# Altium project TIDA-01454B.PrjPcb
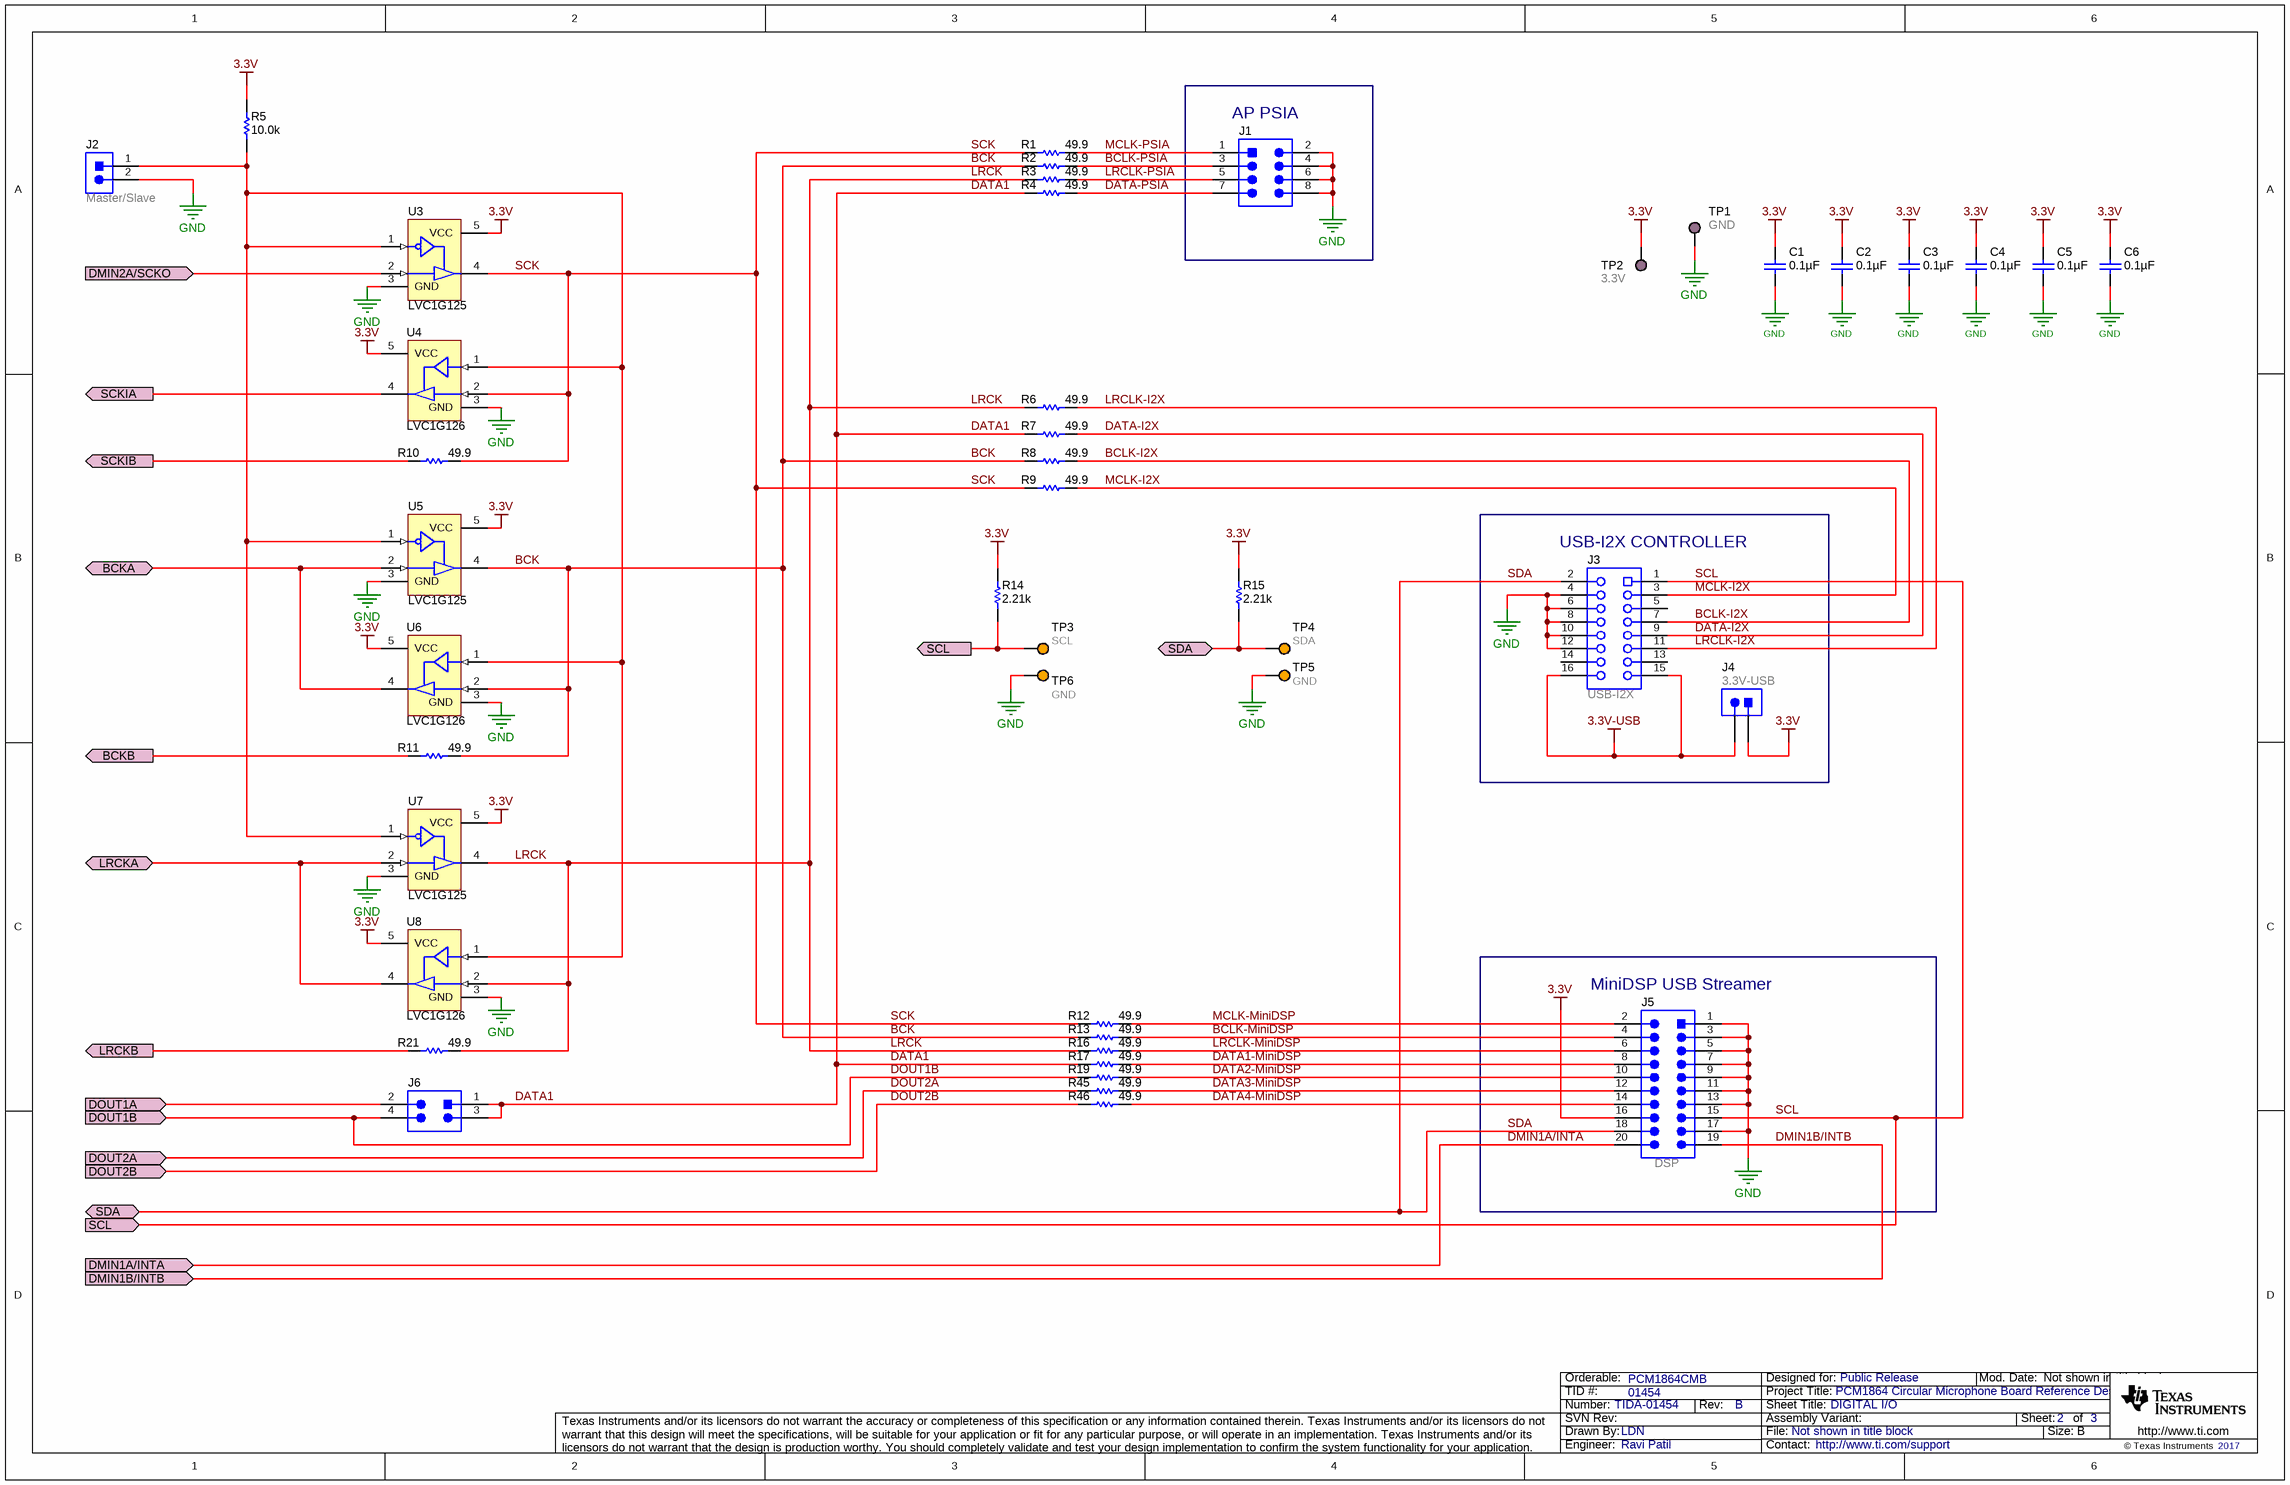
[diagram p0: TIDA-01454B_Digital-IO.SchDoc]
CopyrightYear: 2017; EVM_Orderable: PCM1864CMB; PCB_Layout: LDN; PCB_Rev: B; PRJ_Customer: Public Release; PRJ_Engineer: Ravi Patil; PRJ_Number: TIDA-01454; PRJ_Title: PCM1864 Circular Microphone Board Reference Design; SCH_Rev: B; TechSupport: http://www.ti.com/support; TID: 01454
3 sheets, 209 parts. Net scope: flat (ports and power ports of the same name join across sheets).
Board file: TIDA-01454B_PCB.PcbDoc
Sheets:
  TIDA-01454B_Digital-IO.SchDoc
  TIDA-01454B_Hardware.SchDoc
  TIDA-01454B_Main-IO.SchDoc

## Sheet TIDA-01454B_Digital-IO.SchDoc: DIGITAL I/O
size 431 x 279 mm; Date: Not shown in title block; ApprovedBy: Not shown in title block; CheckedBy: Not shown in title block; Author: Not shown in title block; CompanyName: Not shown in title block; DrawnBy: LDN; Engineer: Not shown in title block; Organization: Not shown in title block; Address1: Not shown in title block; Address2: Not shown in title block; Address3: Not shown in title block; Address4: Not shown in title block; DocumentNumber: 2; Revision: Use project parameter SCH_Rev; SheetNumber: 2; SheetTotal: 3; PageSetup: Record=PageOptions¦CenterHorizontal=True¦CenterVertical=True¦PrintScale=1.00¦XCorrection=1.00¦YCorrection=1.00¦PrintKind=0¦BorderSize=5000000¦LeftOffset=0¦BottomOffset=0¦Orientation=2¦PaperLength=1000¦PaperWidth=1000¦Scale=100¦PaperSource=15¦PrintQuality=600¦MediaType=1¦DitherType=10¦PaperKind=Letter¦PrintScaleMode=1

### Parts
C1  ValueDisplayed: 0.1µF  [0603L]  (hidden comment: GRM188R71C104KA01D)
C2  ValueDisplayed: 0.1µF  [0603L]  (hidden comment: GRM188R71C104KA01D)
C3  ValueDisplayed: 0.1µF  [0603L]  (hidden comment: GRM188R71C104KA01D)
C4  ValueDisplayed: 0.1µF  [0603L]  (hidden comment: GRM188R71C104KA01D)
C5  ValueDisplayed: 0.1µF  [0603L]  (hidden comment: GRM188R71C104KA01D)
C6  ValueDisplayed: 0.1µF  [0603L]  (hidden comment: GRM188R71C104KA01D)
J1  DNP  [CONN_PEC04DAAN]  (value not drawn)
J2  Master/Slave  [Sullins_PBC02SAAN]
J3  USB-I2X  [Sullins_PPPC082LJBN-RC]
J4  3.3V-USB  [Sullins_PBC02SAAN]
J5  DSP  [TSW-110-07-G-D]
J6  PBC02DAAN  [Sullins_PxC02DAAN]  (value not drawn)
R1  ValueDisplayed: 49.9  [0402L]  (hidden comment: RC0402FR-0749R9L)
R2  ValueDisplayed: 49.9  [0402L]  (hidden comment: RC0402FR-0749R9L)
R3  ValueDisplayed: 49.9  [0402L]  (hidden comment: RC0402FR-0749R9L)
R4  ValueDisplayed: 49.9  [0402L]  (hidden comment: RC0402FR-0749R9L)
R5  ValueDisplayed: 10.0k  [0603L]  (hidden comment: ERJ-3EKF1002V)
R6  ValueDisplayed: 49.9  [0402L]  (hidden comment: RC0402FR-0749R9L)
R7  ValueDisplayed: 49.9  [0402L]  (hidden comment: RC0402FR-0749R9L)
R8  ValueDisplayed: 49.9  [0402L]  (hidden comment: RC0402FR-0749R9L)
R9  ValueDisplayed: 49.9  [0402L]  (hidden comment: RC0402FR-0749R9L)
R10  ValueDisplayed: 49.9  [0402L]  (hidden comment: RC0402FR-0749R9L)
R11  ValueDisplayed: 49.9  [0402L]  (hidden comment: RC0402FR-0749R9L)
R12  ValueDisplayed: 49.9  [0402L]  (hidden comment: RC0402FR-0749R9L)
R13  ValueDisplayed: 49.9  [0402L]  (hidden comment: RC0402FR-0749R9L)
R14  ValueDisplayed: 2.21k  [0402L]  (hidden comment: CRCW04022K21FKED)
R15  ValueDisplayed: 2.21k  [0402L]  (hidden comment: CRCW04022K21FKED)
R16  ValueDisplayed: 49.9  [0402L]  (hidden comment: RC0402FR-0749R9L)
R17  ValueDisplayed: 49.9  [0402L]  (hidden comment: RC0402FR-0749R9L)
R19  ValueDisplayed: 49.9  [0402L]  (hidden comment: RC0402FR-0749R9L)
R21  ValueDisplayed: 49.9  [0402L]  (hidden comment: RC0402FR-0749R9L)
R45  ValueDisplayed: 49.9  [0402L]  (hidden comment: RC0402FR-0749R9L)
R46  ValueDisplayed: 49.9  [0402L]  (hidden comment: RC0402FR-0749R9L)
TP1  GND  [TestPoint_50x20-TH]
TP2  3.3V  [TestPoint_50x20-TH]
TP3  SCL  [TestPoint_50x30-TH]
TP4  SDA  [TestPoint_50x30-TH]
TP5  GND  [TestPoint_50x30-TH]
TP6  GND  [TestPoint_50x30-TH]
U3  LVC1G125  [DCK0005A_N]
U4  LVC1G126  [DCK0005A_N]
U5  LVC1G125  [DCK0005A_N]
U6  LVC1G126  [DCK0005A_N]
U7  LVC1G125  [DCK0005A_N]
U8  LVC1G126  [DCK0005A_N]

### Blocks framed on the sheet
AP PSIA: J1
USB-I2X CONTROLLER: J3 J4
MiniDSP USB Streamer: J5

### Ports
BCKA (bidir), BCKB (out), DMIN1A/INTA (in), DMIN1B/INTB (in), DMIN2A/SCKO (in), DOUT1A (in), DOUT1B (in), DOUT2A (in), DOUT2B (in), LRCKA (bidir), LRCKB (out), SCKIA (out), SCKIB (out), SCL (in), SCL (out), SDA (bidir)

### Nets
3.3V: C1.2 C2.2 C3.2 C4.2 C5.2 C6.2 J4.1 J5.16 R5.2 R14.1 R15.1 TP2.1 U3.5(VCC) U4.5(VCC) U5.5(VCC) U6.5(VCC) U7.5(VCC) U8.5(VCC)
3.3V-USB: J3.15 J3.16 J4.2
GND: C1.1 C2.1 C3.1 C4.1 C5.1 C6.1 J1.2 J1.4 J1.6 J1.8 J2.2 J3.4 J3.6 J3.8 J3.10 J3.12 J5.1 J5.3 J5.5 J5.7 J5.9 J5.11 J5.13 J5.17 TP1.1 TP5.1 TP6.1 U3.3(GND) U4.3(GND) U5.3(GND) U6.3(GND) U7.3(GND) U8.3(GND)
BCK: R2.1 R8.1 R11.2 R13.1 U5.4(Y) U6.2(A)
BCKA: U5.2(A) U6.4(Y) ; port BCKA
BCKB: R11.1 ; port BCKB
BCLK-I2X: J3.7 R8.2
BCLK-MiniDSP: J5.4 R13.2
BCLK-PSIA: J1.3 R2.2
DATA1: J6.1 J6.3 R4.1 R7.1 R17.1
DATA1-MiniDSP: J5.8 R17.2
DATA2-MiniDSP: J5.10 R19.2
DATA3-MiniDSP: J5.12 R45.2
DATA4-MiniDSP: J5.14 R46.2
DATA-I2X: J3.9 R7.2
DATA-PSIA: J1.7 R4.2
DMIN1A/INTA: J5.20 ; port DMIN1A/INTA
DMIN1B/INTB: J5.19 ; port DMIN1B/INTB
DMIN2A/SCKO: U3.2(A) ; port DMIN2A/SCKO
DOUT1A: J6.2 ; port DOUT1A
DOUT1B: J6.4 R19.1 ; port DOUT1B
DOUT2A: R45.1 ; port DOUT2A
DOUT2B: R46.1 ; port DOUT2B
LRCK: R3.1 R6.1 R16.1 R21.2 U7.4(Y) U8.2(A)
LRCKA: U7.2(A) U8.4(Y) ; port LRCKA
LRCKB: R21.1 ; port LRCKB
LRCLK-I2X: J3.11 R6.2
LRCLK-MiniDSP: J5.6 R16.2
LRCLK-PSIA: J1.5 R3.2
MCLK-I2X: J3.3 R9.2
MCLK-MiniDSP: J5.2 R12.2
MCLK-PSIA: J1.1 R1.2
SCK: R1.1 R9.1 R10.2 R12.1 U3.4(Y) U4.2(A)
SCKIA: U4.4(Y) ; port SCKIA
SCKIB: R10.1 ; port SCKIB
SCL: J3.1 J5.15 R14.2 TP3.1 ; port SCL
SDA: J3.2 J5.18 R15.2 TP4.1 ; port SDA
NetJ2_1: J2.1 R5.1 U3.1(~{OE}) U4.1(~{OE}) U5.1(~{OE}) U6.1(~{OE}) U7.1(~{OE}) U8.1(~{OE})

Not connected (* = marked no-connect by the designer): J3 5 13 14

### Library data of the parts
C1-C6 = GRM188R71C104KA01D: CAP, CERM, 0.1 µF, 16 V, +/- 10%, X7R, 0603; Manufacturer: MuRata; Polarized: N; CompType: Capacitor; Value: 0.1uF; U/M: EA; Cap_F: 0.0000001; Tolerance_%: 10; Value1: Unknown; VDC_V: 16; Value2: 16V; TaMin_C: -55; TaMax_C: 125; Cap_Case: 0603; SizeArea_mm2: 1.28; SizeAreaWB_mm2: 4.68; SizeX_mm: 1.6; SizeY_mm: 0.8; SizeZ_mm: 1; AEC Category: Q200
J1 = PEC04DAAN: Header, 100mil, 4x2, Tin, TH; Manufacturer: Sullins Connector Solutions; SymbolCreator: a0411947; Pitch_mm: 2.54; Gender: Male; Shrouded: N; Row_Count: 2; Current_A: 3; Voltage_V: 1800; Cert_UL: Y
J2 J4 = PBC02SAAN: Header, 100mil, 2x1, Gold, TH; Manufacturer: Sullins Connector Solutions; SymbolCreator: a0412235; Pitch_mm: 2.54; Gender: Male; Shrouded: N; Row_Count: 1; Current_A: 3; Voltage_V: 1800; Cert_UL: Y
J3 = PPPC082LJBN-RC: Receptacle, 100mil, 8x2, Gold, R/A, TH; Manufacturer: Sullins Connector Solutions; SymbolCreator: a0411947
J5 = TSW-110-07-G-D: Header, 100mil, 10x2, Gold, TH; Manufacturer: Samtec; SymbolCreator: a0412235; Pitch_mm: 2.54; Gender: Male; Shrouded: N; Row_Count: 2; Current_A: 6.3; Voltage_V: 550; Cert_CSA: Y
J6 = PBC02DAAN: Header, 2.54mm, 2x2, Gold, TH; Manufacturer: Sullins Connector Solutions; SymbolCreator: a0412235; Pitch_mm: 2.54; Gender: Male; Shrouded: N; Row_Count: 2; Current_A: 3; Voltage_V: 1800; Cert_UL: Y
R1-R4 R6-R13 R16 R17 R19 R21 R45 R46 = RC0402FR-0749R9L: RES, 49.9, 1%, 0.063 W, 0402; Manufacturer: Yageo America; CompType: Resistor; Value: 49.9; Value_Code: 49R9; Tolerance_%: 1; Power_W: 0.063; Value2: 0.063W; VDC_V: 50; TempCo: 100 ppm/C; SizeArea_mm2: 0.5; SizeZ_mm: 0.6; EIA_Code: E96; U/M: EA; AEC Category: Q200; AEC Qualified: N
R5 = ERJ-3EKF1002V: RES, 10.0 k, 1%, 0.1 W, 0603; Manufacturer: Panasonic; CompType: Resistor; Value: 10.0k; Res_ohm: 10000; Value_Code: 10k0; Tolerance_%: 1; Power_W: 0.1; Value2: 0.1W; VDC_V: 75; TempCo: 100 ppm/C; SizeArea_mm2: 1.28; SizeX_mm: 1.6; SizeY_mm: 0.8; EIA_Code: E96; U/M: EA; AEC Category: Q200
R14 R15 = CRCW04022K21FKED: RES, 2.21 k, 1%, 0.063 W, 0402; Manufacturer: Vishay-Dale; CompType: Resistor; Value: 2.21k; Res_ohm: 2210; Value_Code: 2k21; Tolerance_%: 1; Power_W: 0.063; Value2: 0.063W; VDC_V: 50; TempCo: 100 ppm/C; SizeArea_mm2: 0.5; SizeZ_mm: 0.6; EIA_Code: E96; U/M: EA; AEC Category: Q200
TP1 TP2 = TestPoint_50x20-TH: Test Point, 50x20mils, TH; PartNumber: 5129; Manufacturer: Keystone; SymbolCreator: a0412235; CompType: Test Point Loop; ContactFinish: Silver
TP3-TP6 = TestPoint_50x30-TH: Test Point, 50x30mils, TH; PartNumber: 5129; Manufacturer: Keystone; SymbolCreator: a0412235; CompType: Test Point Loop; ContactFinish: Silver
U3 U5 U7 = SN74LVC1G125DCKR: Single Bus Buffer Gate With 3-State Output, DCK0005A; Alternate PartNumber: SN74LVC1G125DCKT; Manufacturer: Texas Instruments; SymbolCreator: Altium; CompType: IC; U/M: EA
U4 U6 U8 = SN74LVC1G126DCKR: Single Bus Buffer Gate With 3-State Output, DCK0005A; Alternate PartNumber: SN74LVC1G126DCKT; Manufacturer: Texas Instruments; SymbolCreator: Altium; SizeArea_mm2: 4.2; SizeAreaWB_mm2: 9.3; SizeX_mm: 2.1; SizeY_mm: 2; SizeZ_mm: 1.1; CompType: IC; U/M: EA

## Sheet TIDA-01454B_Hardware.SchDoc
size Letter; Date: Not shown in title block; ApprovedBy: Not shown in title block; CheckedBy: Not shown in title block; Author: Not shown in title block; CompanyName: Not shown in title block; Engineer: Not shown in title block; Organization: Not shown in title block; Address1: Not shown in title block; Address2: Not shown in title block; Address3: Not shown in title block; Address4: Not shown in title block; DocumentNumber: 3; Revision: Use project parameter SCH_Rev; SheetNumber: 3; SheetTotal: 3; PageSetup: Record=PageOptions¦CenterHorizontal=True¦CenterVertical=True¦PrintScale=1.00¦XCorrection=1.00¦YCorrection=1.00¦PrintKind=0¦BorderSize=5000000¦LeftOffset=0¦BottomOffset=0¦Orientation=2¦PaperLength=1000¦PaperWidth=1000¦Scale=100¦PaperSource=15¦PrintQuality=600¦MediaType=1¦DitherType=10¦PaperKind=Letter¦PrintScaleMode=1
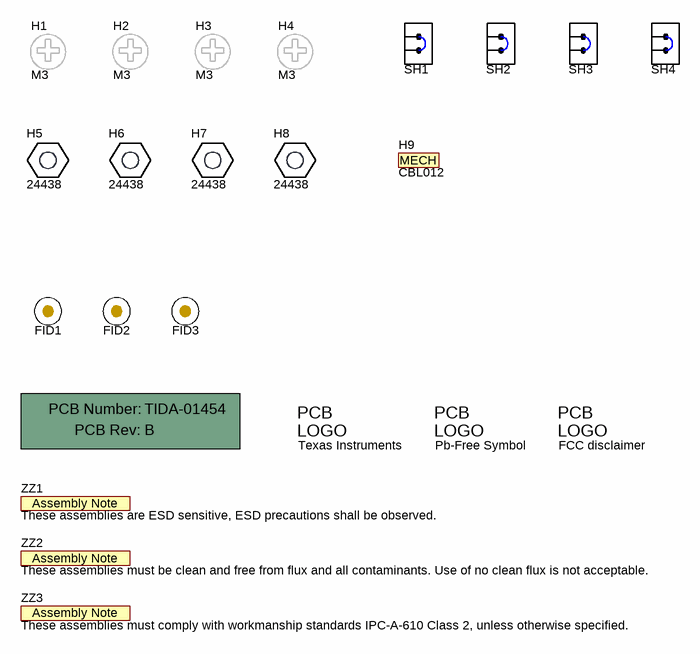
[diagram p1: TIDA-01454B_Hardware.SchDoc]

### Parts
!PCB1  Printed Circuit Board  (value not drawn)  (mechanical)
FID1  Fiducial  [Fiducial10-20]  (value not drawn)
FID2  Fiducial  [Fiducial10-20]  (value not drawn)
FID3  Fiducial  [Fiducial10-20]  (value not drawn)
H1  M3  [BuildingFastener_MPMS_003_0005_PH]
H2  M3  [BuildingFastener_MPMS_003_0005_PH]
H3  M3  [BuildingFastener_MPMS_003_0005_PH]
H4  M3  [BuildingFastener_MPMS_003_0005_PH]
H5  24438  [Keystone24438]
H6  24438  [Keystone24438]
H7  24438  [Keystone24438]
H8  24438  [Keystone24438]
H9  CBL012  (mechanical)
Logo1  Texas Instruments  [TI_Stacked_Overlay_Small]  (no BOM)
Logo2  Pb-Free Symbol  [Pb-Free_Overlay_Small]  (no BOM)
Logo3  FCC disclaimer  [FCC_disclaimer_stacked]  (no BOM)
SH1  SNT-100-BK-G  [SNT-100-BK-G]  (value not drawn)
SH2  SNT-100-BK-G  [SNT-100-BK-G]  (value not drawn)
SH3  SNT-100-BK-G  [SNT-100-BK-G]  (value not drawn)
SH4  SNT-100-BK-G  [SNT-100-BK-G]  (value not drawn)
ZZ1  These assemblies are ESD sensitive, ESD precautions shall be observed.  [AssemblyNote]  (no BOM)
ZZ2  These assemblies must be clean and free from flux and all contaminants. Use of no clean flux is not acceptable.  [AssemblyNote]  (no BOM)
ZZ3  These assemblies must comply with workmanship standards IPC-A-610 Class 2, unless otherwise specified.  [AssemblyNote]  (no BOM)

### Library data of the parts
!PCB1 = PCB: Manufacturer: Any; PartNumber: TIDA-01454; SymbolCreator: a0412235
FID1-FID3 = Fiducial: Fiducial mark.  There is nothing to buy or mount.; SymbolCreator: codlsc
H1-H4 = MPMS 003 0005 PH: MACHINE SCREW PAN PHILLIPS M3 5mm; Manufacturer: B&F Fastener Supply; CompType: Hardware
H5-H8 = 24438: Standoff, Hex,25mm Length, M3, Aluminum; Manufacturer: Keystone; SymbolCreator: a0412235; CompType: Hardware
H9 = MechPart: CBL012 Cable Assembly; Manufacturer: Used in BOM report; SymbolCreator: codlsc; CompType: Mechanical; U/M: EA
Logo1 = TI_Logo: Texas Instrument Corporate Signature; SymbolCreator: codlsc
Logo2 = Pb-Free: SymbolCreator: a0412235
Logo3 = FCC_disclaimer: SymbolCreator: codlsc
SH1-SH4 = SNT-100-BK-G: Shunt, 100mil, Gold plated, Black; Manufacturer: Samtec; Alternate Manufacturer: 3M; Alternate PartNumber: 969102-0000-DA; Value: 1x2; Note: You can "mate" this to a header by matching the designator.  i.e. use SH-J3 for header J3
ZZ1-ZZ3 = AssemblyNote: SymbolCreator: codlsc

## Sheet TIDA-01454B_Main-IO.SchDoc: Main I/O
size 538 x 342 mm; Date: Not shown in title block; ApprovedBy: Not shown in title block; CheckedBy: Not shown in title block; Author: Not shown in title block; CompanyName: Not shown in title block; DrawnBy: LDN; Engineer: Not shown in title block; Organization: Not shown in title block; Address1: Not shown in title block; Address2: Not shown in title block; Address3: Not shown in title block; Address4: Not shown in title block; DocumentNumber: 1; Revision: Use project parameter SCH_Rev; SheetNumber: 1; SheetTotal: 3; PageSetup: Record=PageOptions¦CenterHorizontal=True¦CenterVertical=True¦PrintScale=1.00¦XCorrection=1.00¦YCorrection=1.00¦PrintKind=0¦BorderSize=5000000¦LeftOffset=0¦BottomOffset=0¦Orientation=2¦PaperLength=1000¦PaperWidth=1000¦Scale=100¦PaperSource=15¦PrintQuality=600¦MediaType=1¦DitherType=10¦PaperKind=Letter¦PrintScaleMode=1
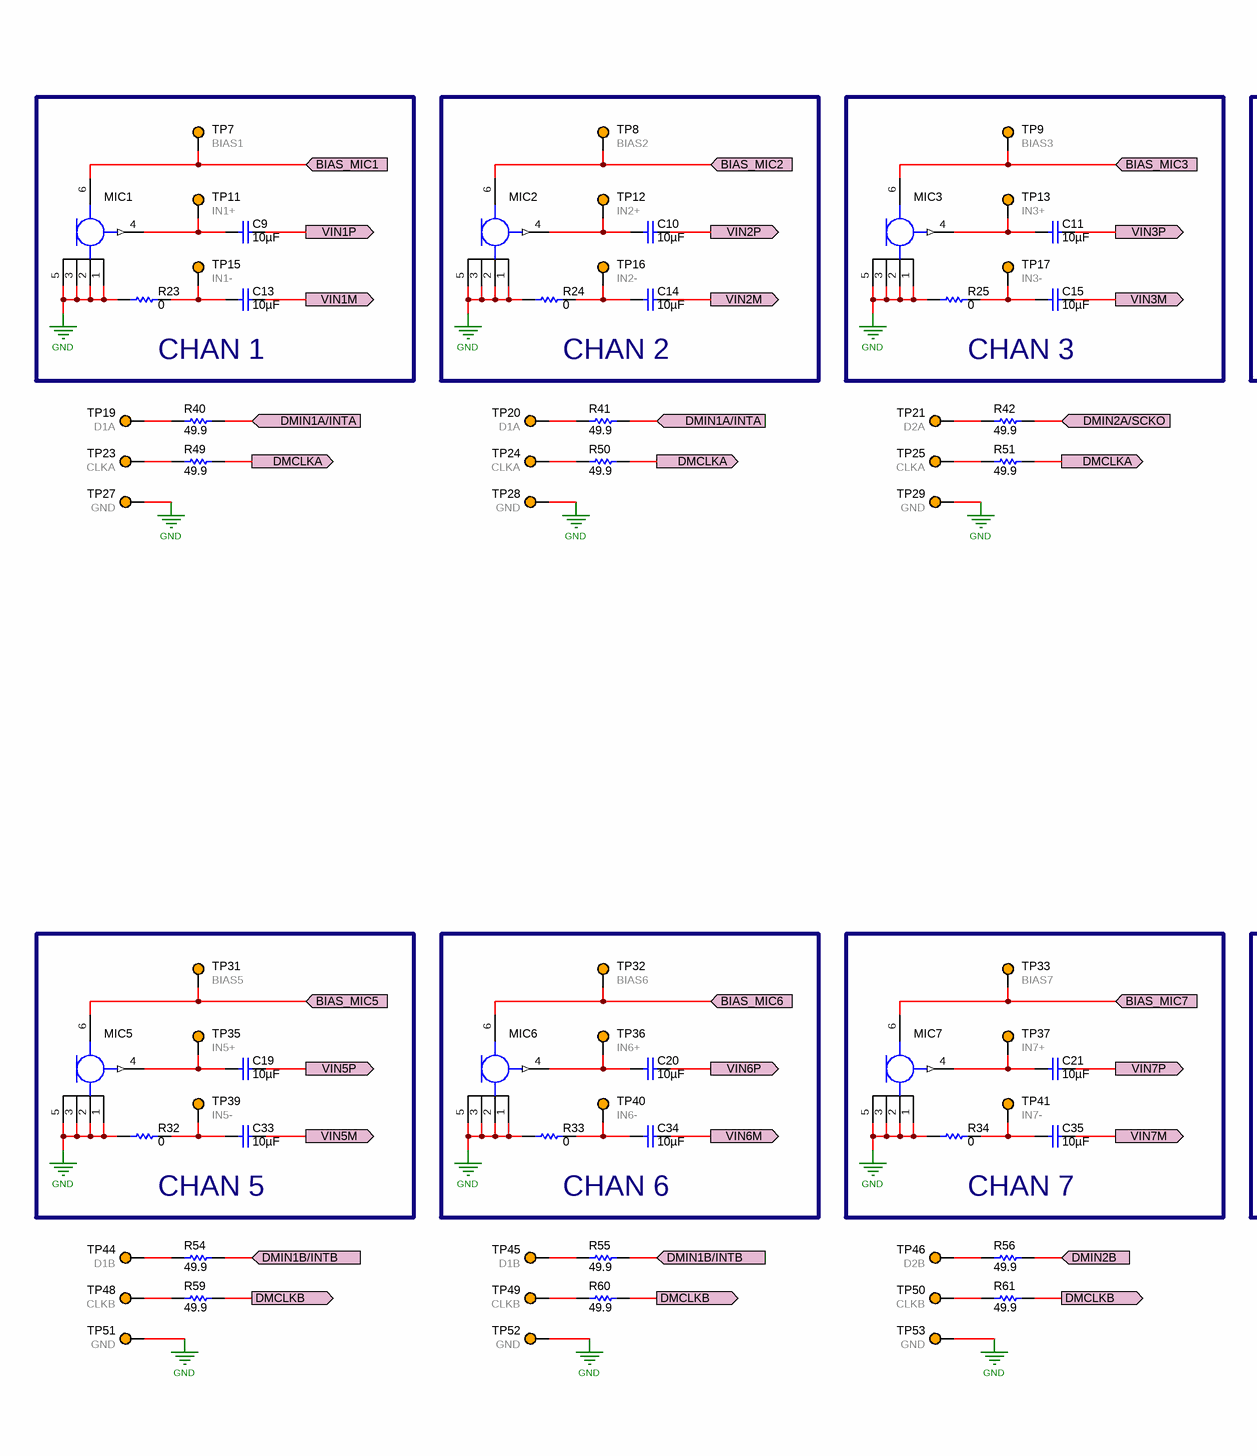
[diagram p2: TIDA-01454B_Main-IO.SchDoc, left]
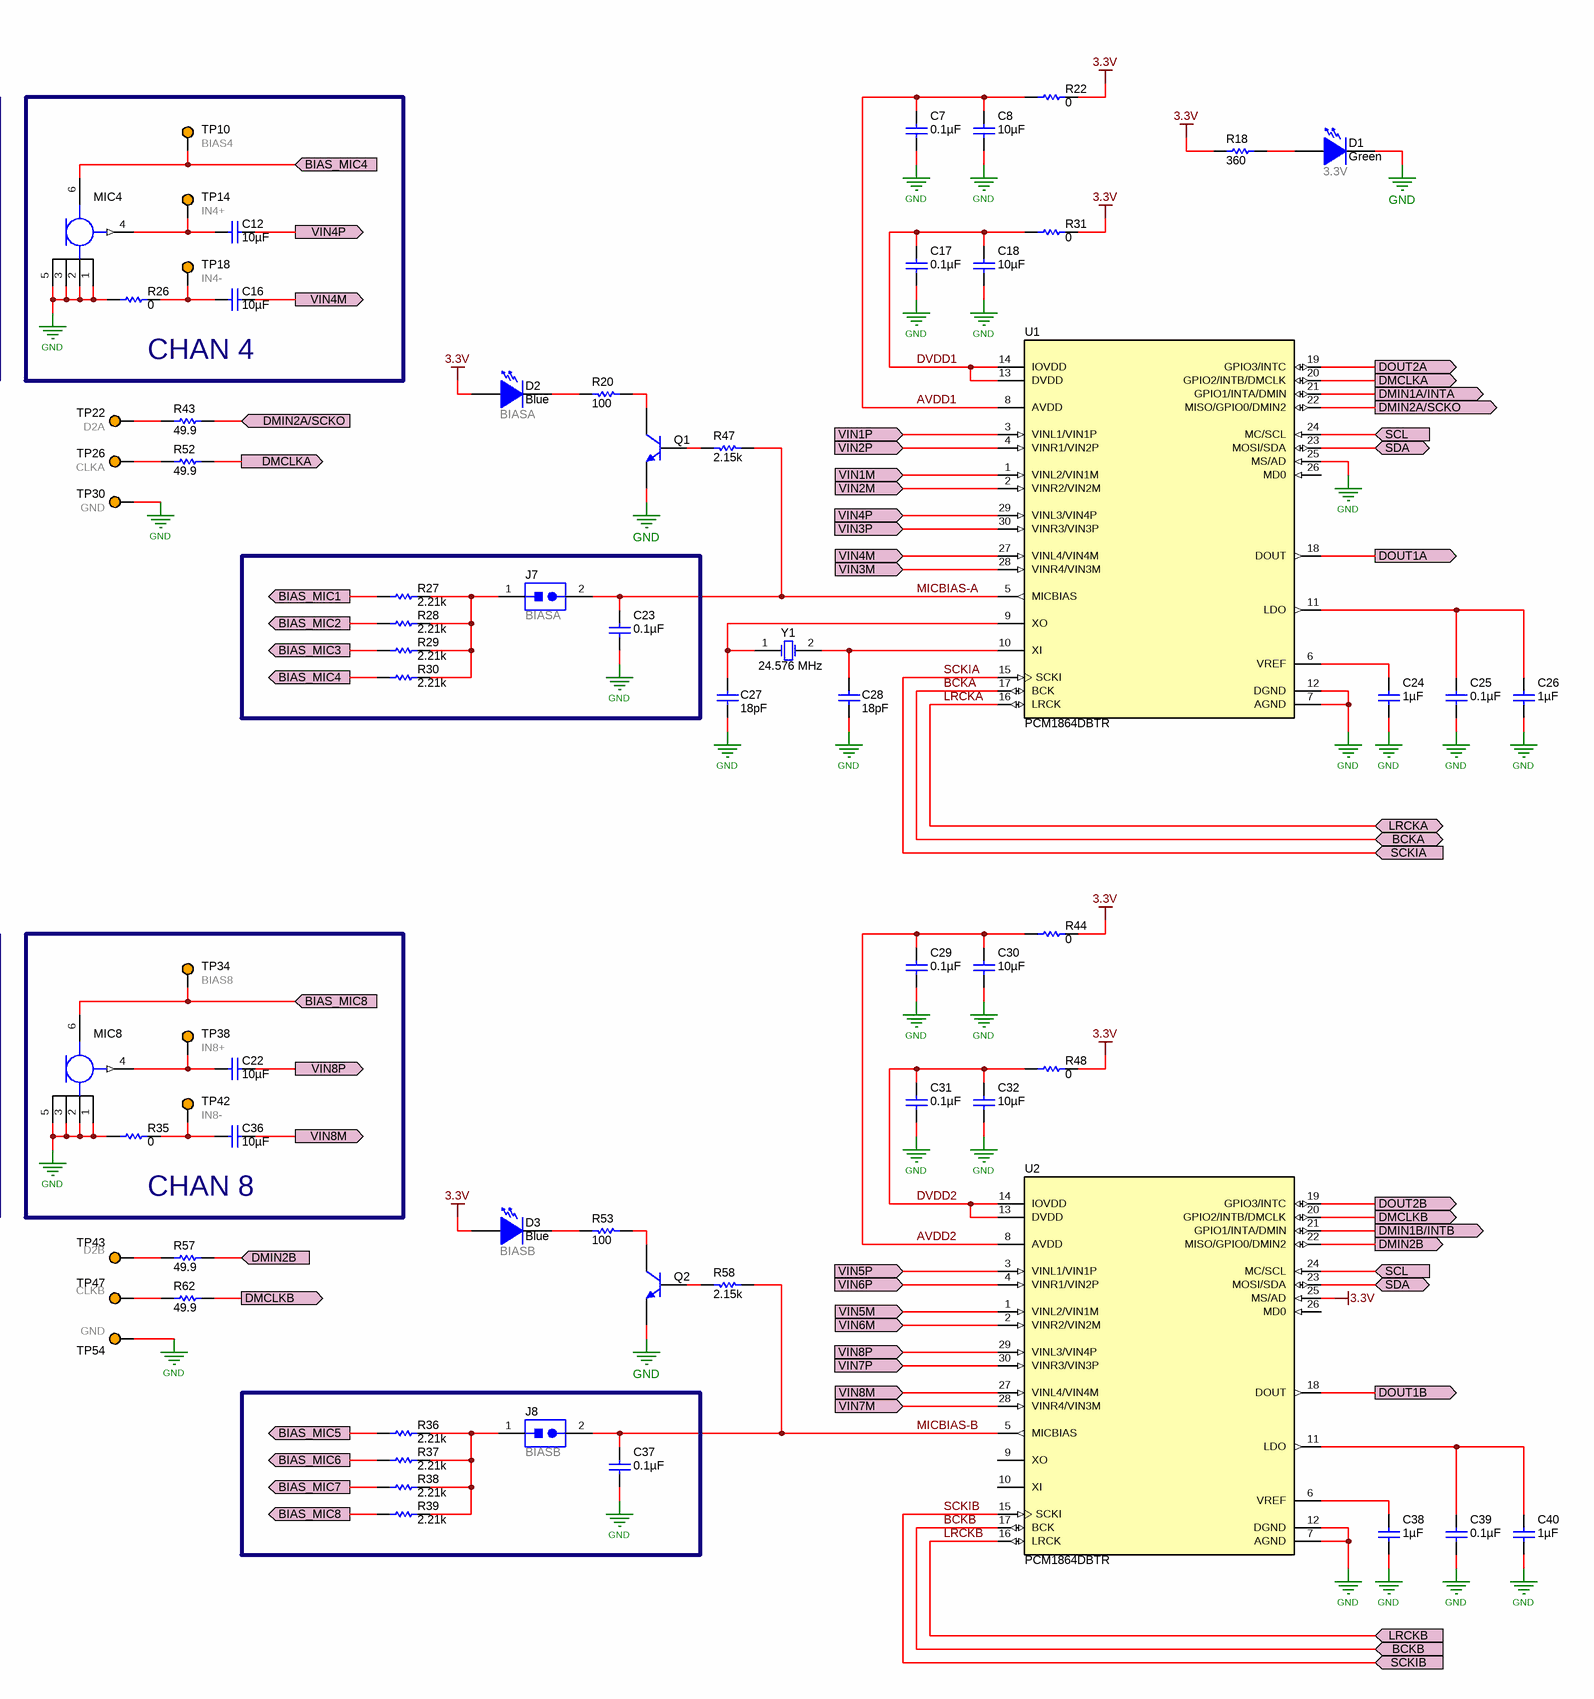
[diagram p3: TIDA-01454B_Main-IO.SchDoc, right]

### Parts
C7  ValueDisplayed: 0.1µF  [0603L]  (hidden comment: GRM188R71C104KA01D)
C8  ValueDisplayed: 10µF  [0805_KTR]  (hidden comment: GRM21BR71A106KE51K)
C9  ValueDisplayed: 10µF  [0805_KTR]  (hidden comment: GRM21BR71A106KE51K)
C10  ValueDisplayed: 10µF  [0805_KTR]  (hidden comment: GRM21BR71A106KE51K)
C11  ValueDisplayed: 10µF  [0805_KTR]  (hidden comment: GRM21BR71A106KE51K)
C12  ValueDisplayed: 10µF  [0805_KTR]  (hidden comment: GRM21BR71A106KE51K)
C13  ValueDisplayed: 10µF  [0805_KTR]  (hidden comment: GRM21BR71A106KE51K)
C14  ValueDisplayed: 10µF  [0805_KTR]  (hidden comment: GRM21BR71A106KE51K)
C15  ValueDisplayed: 10µF  [0805_KTR]  (hidden comment: GRM21BR71A106KE51K)
C16  ValueDisplayed: 10µF  [0805_KTR]  (hidden comment: GRM21BR71A106KE51K)
C17  ValueDisplayed: 0.1µF  [0603L]  (hidden comment: GRM188R71C104KA01D)
C18  ValueDisplayed: 10µF  [0805_KTR]  (hidden comment: GRM21BR71A106KE51K)
C19  ValueDisplayed: 10µF  [0805_KTR]  (hidden comment: GRM21BR71A106KE51K)
C20  ValueDisplayed: 10µF  [0805_KTR]  (hidden comment: GRM21BR71A106KE51K)
C21  ValueDisplayed: 10µF  [0805_KTR]  (hidden comment: GRM21BR71A106KE51K)
C22  ValueDisplayed: 10µF  [0805_KTR]  (hidden comment: GRM21BR71A106KE51K)
C23  ValueDisplayed: 0.1µF  [0603L]  (hidden comment: GRM188R71C104KA01D)
C24  ValueDisplayed: 1µF  [0603L]  (hidden comment: GRM188R71C105KA12D)
C25  ValueDisplayed: 0.1µF  [0603L]  (hidden comment: GRM188R71C104KA01D)
C26  ValueDisplayed: 1µF  [0603L]  (hidden comment: GRM188R71C105KA12D)
C27  ValueDisplayed: 18pF  [0603L]  (hidden comment: GRM1885C1H180JA01D)
C28  ValueDisplayed: 18pF  [0603L]  (hidden comment: GRM1885C1H180JA01D)
C29  ValueDisplayed: 0.1µF  [0603L]  (hidden comment: GRM188R71C104KA01D)
C30  ValueDisplayed: 10µF  [0805_KTR]  (hidden comment: GRM21BR71A106KE51K)
C31  ValueDisplayed: 0.1µF  [0603L]  (hidden comment: GRM188R71C104KA01D)
C32  ValueDisplayed: 10µF  [0805_KTR]  (hidden comment: GRM21BR71A106KE51K)
C33  ValueDisplayed: 10µF  [0805_KTR]  (hidden comment: GRM21BR71A106KE51K)
C34  ValueDisplayed: 10µF  [0805_KTR]  (hidden comment: GRM21BR71A106KE51K)
C35  ValueDisplayed: 10µF  [0805_KTR]  (hidden comment: GRM21BR71A106KE51K)
C36  ValueDisplayed: 10µF  [0805_KTR]  (hidden comment: GRM21BR71A106KE51K)
C37  ValueDisplayed: 0.1µF  [0603L]  (hidden comment: GRM188R71C104KA01D)
C38  ValueDisplayed: 1µF  [0603L]  (hidden comment: GRM188R71C105KA12D)
C39  ValueDisplayed: 0.1µF  [0603L]  (hidden comment: GRM188R71C104KA01D)
C40  ValueDisplayed: 1µF  [0603L]  (hidden comment: GRM188R71C105KA12D)
D1  3.3V  value Green  [LED_LTST-C171]
D2  BIASA  value Blue  [LED_SMLP12_BLUE]
D3  BIASB  value Blue  [LED_SMLP12_BLUE]
J7  BIASA  [Sullins_PBC02SAAN]
J8  BIASB  [Sullins_PBC02SAAN]
MIC1  SPH1642HT5H-1  [Knowles_SPH1642HT5H-1]  (value not drawn)
MIC2  SPH1642HT5H-1  [Knowles_SPH1642HT5H-1]  (value not drawn)
MIC3  SPH1642HT5H-1  [Knowles_SPH1642HT5H-1]  (value not drawn)
MIC4  SPH1642HT5H-1  [Knowles_SPH1642HT5H-1]  (value not drawn)
MIC5  SPH1642HT5H-1  [Knowles_SPH1642HT5H-1]  (value not drawn)
MIC6  SPH1642HT5H-1  [Knowles_SPH1642HT5H-1]  (value not drawn)
MIC7  SPH1642HT5H-1  [Knowles_SPH1642HT5H-1]  (value not drawn)
MIC8  SPH1642HT5H-1  [Knowles_SPH1642HT5H-1]  (value not drawn)
Q1  MMBT2222A  [SOT-23]  (value not drawn)
Q2  MMBT2222A  [SOT-23]  (value not drawn)
R18  value 360  [0402L]  (hidden comment: CRCW0402360RJNED)
R20  ValueDisplayed: 100  [0402L]  (hidden comment: ERJ-2RKF1000X)
R22  ValueDisplayed: 0  [0603L]  (hidden comment: CRCW06030000Z0EA)
R23  ValueDisplayed: 0  [0603L]  (hidden comment: CRCW06030000Z0EA)
R24  ValueDisplayed: 0  [0603L]  (hidden comment: CRCW06030000Z0EA)
R25  ValueDisplayed: 0  [0603L]  (hidden comment: CRCW06030000Z0EA)
R26  ValueDisplayed: 0  [0603L]  (hidden comment: CRCW06030000Z0EA)
R27  ValueDisplayed: 2.21k  [0402L]  (hidden comment: CRCW04022K21FKED)
R28  ValueDisplayed: 2.21k  [0402L]  (hidden comment: CRCW04022K21FKED)
R29  ValueDisplayed: 2.21k  [0402L]  (hidden comment: CRCW04022K21FKED)
R30  ValueDisplayed: 2.21k  [0402L]  (hidden comment: CRCW04022K21FKED)
R31  ValueDisplayed: 0  [0603L]  (hidden comment: CRCW06030000Z0EA)
R32  ValueDisplayed: 0  [0603L]  (hidden comment: CRCW06030000Z0EA)
R33  ValueDisplayed: 0  [0603L]  (hidden comment: CRCW06030000Z0EA)
R34  ValueDisplayed: 0  [0603L]  (hidden comment: CRCW06030000Z0EA)
R35  ValueDisplayed: 0  [0603L]  (hidden comment: CRCW06030000Z0EA)
R36  ValueDisplayed: 2.21k  [0402L]  (hidden comment: CRCW04022K21FKED)
R37  ValueDisplayed: 2.21k  [0402L]  (hidden comment: CRCW04022K21FKED)
R38  ValueDisplayed: 2.21k  [0402L]  (hidden comment: CRCW04022K21FKED)
R39  ValueDisplayed: 2.21k  [0402L]  (hidden comment: CRCW04022K21FKED)
R40  ValueDisplayed: 49.9  [0402L]  (hidden comment: RC0402FR-0749R9L)
R41  ValueDisplayed: 49.9  [0402L]  (hidden comment: RC0402FR-0749R9L)
R42  ValueDisplayed: 49.9  [0402L]  (hidden comment: RC0402FR-0749R9L)
R43  ValueDisplayed: 49.9  [0402L]  (hidden comment: RC0402FR-0749R9L)
R44  ValueDisplayed: 0  [0603L]  (hidden comment: CRCW06030000Z0EA)
R47  ValueDisplayed: 2.15k  [0402L]  (hidden comment: CRCW04022K15FKED)
R48  ValueDisplayed: 0  [0603L]  (hidden comment: CRCW06030000Z0EA)
R49  ValueDisplayed: 49.9  [0402L]  (hidden comment: RC0402FR-0749R9L)
R50  ValueDisplayed: 49.9  [0402L]  (hidden comment: RC0402FR-0749R9L)
R51  ValueDisplayed: 49.9  [0402L]  (hidden comment: RC0402FR-0749R9L)
R52  ValueDisplayed: 49.9  [0402L]  (hidden comment: RC0402FR-0749R9L)
R53  ValueDisplayed: 100  [0402L]  (hidden comment: ERJ-2RKF1000X)
R54  ValueDisplayed: 49.9  [0402L]  (hidden comment: RC0402FR-0749R9L)
R55  ValueDisplayed: 49.9  [0402L]  (hidden comment: RC0402FR-0749R9L)
R56  ValueDisplayed: 49.9  [0402L]  (hidden comment: RC0402FR-0749R9L)
R57  ValueDisplayed: 49.9  [0402L]  (hidden comment: RC0402FR-0749R9L)
R58  ValueDisplayed: 2.15k  [0402L]  (hidden comment: CRCW04022K15FKED)
R59  ValueDisplayed: 49.9  [0402L]  (hidden comment: RC0402FR-0749R9L)
R60  ValueDisplayed: 49.9  [0402L]  (hidden comment: RC0402FR-0749R9L)
R61  ValueDisplayed: 49.9  [0402L]  (hidden comment: RC0402FR-0749R9L)
R62  ValueDisplayed: 49.9  [0402L]  (hidden comment: RC0402FR-0749R9L)
TP7  BIAS1  [TestPoint_50x30-TH]
TP8  BIAS2  [TestPoint_50x30-TH]
TP9  BIAS3  [TestPoint_50x30-TH]
TP10  BIAS4  [TestPoint_50x30-TH]
TP11  IN1+  [TestPoint_50x30-TH]
TP12  IN2+  [TestPoint_50x30-TH]
TP13  IN3+  [TestPoint_50x30-TH]
TP14  IN4+  [TestPoint_50x30-TH]
TP15  IN1-  [TestPoint_50x30-TH]
TP16  IN2-  [TestPoint_50x30-TH]
TP17  IN3-  [TestPoint_50x30-TH]
TP18  IN4-  [TestPoint_50x30-TH]
TP19  D1A  [TestPoint_50x30-TH]
TP20  D1A  [TestPoint_50x30-TH]
TP21  D2A  [TestPoint_50x30-TH]
TP22  D2A  [TestPoint_50x30-TH]
TP23  CLKA  [TestPoint_50x30-TH]
TP24  CLKA  [TestPoint_50x30-TH]
TP25  CLKA  [TestPoint_50x30-TH]
TP26  CLKA  [TestPoint_50x30-TH]
TP27  GND  [TestPoint_50x30-TH]
TP28  GND  [TestPoint_50x30-TH]
TP29  GND  [TestPoint_50x30-TH]
TP30  GND  [TestPoint_50x30-TH]
TP31  BIAS5  [TestPoint_50x30-TH]
TP32  BIAS6  [TestPoint_50x30-TH]
TP33  BIAS7  [TestPoint_50x30-TH]
TP34  BIAS8  [TestPoint_50x30-TH]
TP35  IN5+  [TestPoint_50x30-TH]
TP36  IN6+  [TestPoint_50x30-TH]
TP37  IN7+  [TestPoint_50x30-TH]
TP38  IN8+  [TestPoint_50x30-TH]
TP39  IN5-  [TestPoint_50x30-TH]
TP40  IN6-  [TestPoint_50x30-TH]
TP41  IN7-  [TestPoint_50x30-TH]
TP42  IN8-  [TestPoint_50x30-TH]
TP43  D2B  [TestPoint_50x30-TH]
TP44  D1B  [TestPoint_50x30-TH]
TP45  D1B  [TestPoint_50x30-TH]
TP46  D2B  [TestPoint_50x30-TH]
TP47  CLKB  [TestPoint_50x30-TH]
TP48  CLKB  [TestPoint_50x30-TH]
TP49  CLKB  [TestPoint_50x30-TH]
TP50  CLKB  [TestPoint_50x30-TH]
TP51  GND  [TestPoint_50x30-TH]
TP52  GND  [TestPoint_50x30-TH]
TP53  GND  [TestPoint_50x30-TH]
TP54  GND  [TestPoint_50x30-TH]
U1  PCM1864DBTR  [DBT0030A_N]
U2  PCM1864DBTR  [DBT0030A_N]
Y1  Frequency: 24.576 MHz  [TXC_9B]  (hidden comment: 9B-24.576MEEJ-B)

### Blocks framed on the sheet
CHAN 1: C9 C13 MIC1 R23 TP7 TP11 TP15
CHAN 2: C10 C14 MIC2 R24 TP8 TP12 TP16
CHAN 3: C11 C15 MIC3 R25 TP9 TP13 TP17
CHAN 4: C12 C16 MIC4 R26 TP10 TP14 TP18
CHAN 5: C19 C33 MIC5 R32 TP31 TP35 TP39
CHAN 6: C20 C34 MIC6 R33 TP32 TP36 TP40
CHAN 7: C21 C35 MIC7 R34 TP33 TP37 TP41
CHAN 8: C22 C36 MIC8 R35 TP34 TP38 TP42

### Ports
BCKA (bidir), BCKB (in), BIAS_MIC1 (in), BIAS_MIC1 (out), BIAS_MIC2 (in), BIAS_MIC2 (out), BIAS_MIC3 (in), BIAS_MIC3 (out), BIAS_MIC4 (in), BIAS_MIC4 (out), BIAS_MIC5 (in), BIAS_MIC5 (out), BIAS_MIC6 (in), BIAS_MIC6 (out), BIAS_MIC7 (in), BIAS_MIC7 (out), BIAS_MIC8 (in), BIAS_MIC8 (out), DMCLKA (out), DMCLKB (out), DMIN1A/INTA (in), DMIN1A/INTA (out), DMIN1B/INTB (in), DMIN1B/INTB (out), DMIN2A/SCKO (in), DMIN2A/SCKO (out), DMIN2B (in), DMIN2B (out), DOUT1A (out), DOUT1B (out), DOUT2A (out), DOUT2B (out), LRCKA (bidir), LRCKB (in), SCKIA (in), SCKIB (in), SCL (in), SDA (bidir), VIN1M (in), VIN1M (out), VIN1P (in), VIN1P (out), VIN2M (in), VIN2M (out), VIN2P (in), VIN2P (out), VIN3M (in), VIN3M (out), VIN3P (in), VIN3P (out), VIN4M (in), VIN4M (out), VIN4P (in), VIN4P (out), VIN5M (in), VIN5M (out), VIN5P (in), VIN5P (out), VIN6M (in), VIN6M (out), VIN6P (in), VIN6P (out), VIN7M (in), VIN7M (out), VIN7P (in), VIN7P (out), VIN8M (in), VIN8M (out), VIN8P (in), VIN8P (out)

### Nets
3.3V: D2.1(A) D3.1(A) R18.2 R22.1 R31.1 R44.1 R48.1 U2.25(MS/AD)
GND: C7.1 C8.1 C17.1 C18.1 C23.1 C24.2 C25.1 C26.2 C27.2 C28.2 C29.1 C30.1 C31.1 C32.1 C37.1 C38.2 C39.1 C40.2 D1.2(K) MIC1.1(GND) MIC1.2(GND) MIC1.3(GND) MIC1.5(GND) MIC2.1(GND) MIC2.2(GND) MIC2.3(GND) MIC2.5(GND) MIC3.1(GND) MIC3.2(GND) MIC3.3(GND) MIC3.5(GND) MIC4.1(GND) MIC4.2(GND) MIC4.3(GND) MIC4.5(GND) MIC5.1(GND) MIC5.2(GND) MIC5.3(GND) MIC5.5(GND) MIC6.1(GND) MIC6.2(GND) MIC6.3(GND) MIC6.5(GND) MIC7.1(GND) MIC7.2(GND) MIC7.3(GND) MIC7.5(GND) MIC8.1(GND) MIC8.2(GND) MIC8.3(GND) MIC8.5(GND) Q1.2(E) Q2.2(E) R23.2 R24.2 R25.2 R26.2 R32.2 R33.2 R34.2 R35.2 TP27.1 TP28.1 TP29.1 TP30.1 TP51.1 TP52.1 TP53.1 TP54.1 U1.7(AGND) U1.12(DGND) U1.25(MS/AD) U2.7(AGND) U2.12(DGND)
AVDD1: C7.2 C8.2 R22.2 U1.8(AVDD)
AVDD2: C29.2 C30.2 R44.2 U2.8(AVDD)
BCKA: U1.17(BCK) ; port BCKA
BCKB: U2.17(BCK) ; port BCKB
BIAS_MIC1: MIC1.6(VDD) R27.2 TP7.1 ; port BIAS_MIC1
BIAS_MIC2: MIC2.6(VDD) R28.2 TP8.1 ; port BIAS_MIC2
BIAS_MIC3: MIC3.6(VDD) R29.2 TP9.1 ; port BIAS_MIC3
BIAS_MIC4: MIC4.6(VDD) R30.2 TP10.1 ; port BIAS_MIC4
BIAS_MIC5: MIC5.6(VDD) R36.2 TP31.1 ; port BIAS_MIC5
BIAS_MIC6: MIC6.6(VDD) R37.2 TP32.1 ; port BIAS_MIC6
BIAS_MIC7: MIC7.6(VDD) R38.2 TP33.1 ; port BIAS_MIC7
BIAS_MIC8: MIC8.6(VDD) R39.2 TP34.1 ; port BIAS_MIC8
DMCLKA: R49.1 R50.1 R51.1 R52.1 U1.20(GPIO2/INTB/DMCLK) ; port DMCLKA
DMCLKB: R59.1 R60.1 R61.1 R62.1 U2.20(GPIO2/INTB/DMCLK) ; port DMCLKB
DMIN1A/INTA: R40.1 R41.1 U1.21(GPIO1/INTA/DMIN) ; port DMIN1A/INTA
DMIN1B/INTB: R54.1 R55.1 U2.21(GPIO1/INTA/DMIN) ; port DMIN1B/INTB
DMIN2A/SCKO: R42.1 R43.1 U1.22(MISO/GPIO0/DMIN2) ; port DMIN2A/SCKO
DMIN2B: R56.1 R57.1 U2.22(MISO/GPIO0/DMIN2) ; port DMIN2B
DOUT1A: U1.18(DOUT) ; port DOUT1A
DOUT1B: U2.18(DOUT) ; port DOUT1B
DOUT2A: U1.19(GPIO3/INTC) ; port DOUT2A
DOUT2B: U2.19(GPIO3/INTC) ; port DOUT2B
DVDD1: C17.2 C18.2 R31.2 U1.13(DVDD) U1.14(IOVDD)
DVDD2: C31.2 C32.2 R48.2 U2.13(DVDD) U2.14(IOVDD)
LRCKA: U1.16(LRCK) ; port LRCKA
LRCKB: U2.16(LRCK) ; port LRCKB
MICBIAS-A: C23.2 J7.2 R47.2 U1.5(MICBIAS)
MICBIAS-B: C37.2 J8.2 R58.2 U2.5(MICBIAS)
SCKIA: U1.15(SCKI) ; port SCKIA
SCKIB: U2.15(SCKI) ; port SCKIB
SCL: U1.24(MC/SCL) U2.24(MC/SCL) ; port SCL
SDA: U1.23(MOSI/SDA) U2.23(MOSI/SDA) ; port SDA
VIN1M: C13.1 U1.1(VINL2/VIN1M) ; port VIN1M
VIN1P: C9.1 U1.3(VINL1/VIN1P) ; port VIN1P
VIN2M: C14.1 U1.2(VINR2/VIN2M) ; port VIN2M
VIN2P: C10.1 U1.4(VINR1/VIN2P) ; port VIN2P
VIN3M: C15.1 U1.28(VINR4/VIN3M) ; port VIN3M
VIN3P: C11.1 U1.30(VINR3/VIN3P) ; port VIN3P
VIN4M: C16.1 U1.27(VINL4/VIN4M) ; port VIN4M
VIN4P: C12.1 U1.29(VINL3/VIN4P) ; port VIN4P
VIN5M: C33.1 U2.1(VINL2/VIN1M) ; port VIN5M
VIN5P: C19.1 U2.3(VINL1/VIN1P) ; port VIN5P
VIN6M: C34.1 U2.2(VINR2/VIN2M) ; port VIN6M
VIN6P: C20.1 U2.4(VINR1/VIN2P) ; port VIN6P
VIN7M: C35.1 U2.28(VINR4/VIN3M) ; port VIN7M
VIN7P: C21.1 U2.30(VINR3/VIN3P) ; port VIN7P
VIN8M: C36.1 U2.27(VINL4/VIN4M) ; port VIN8M
VIN8P: C22.1 U2.29(VINL3/VIN4P) ; port VIN8P
NetC9_2: C9.2 MIC1.4(OUTPUT) TP11.1
NetC10_2: C10.2 MIC2.4(OUTPUT) TP12.1
NetC11_2: C11.2 MIC3.4(OUTPUT) TP13.1
NetC12_2: C12.2 MIC4.4(OUTPUT) TP14.1
NetC13_2: C13.2 R23.1 TP15.1
NetC14_2: C14.2 R24.1 TP16.1
NetC15_2: C15.2 R25.1 TP17.1
NetC16_2: C16.2 R26.1 TP18.1
NetC19_2: C19.2 MIC5.4(OUTPUT) TP35.1
NetC20_2: C20.2 MIC6.4(OUTPUT) TP36.1
NetC21_2: C21.2 MIC7.4(OUTPUT) TP37.1
NetC22_2: C22.2 MIC8.4(OUTPUT) TP38.1
NetC24_1: C24.1 U1.6(VREF)
NetC25_2: C25.2 C26.1 U1.11(LDO)
NetC27_1: C27.1 U1.9(XO) Y1.1(OSC1)
NetC28_1: C28.1 U1.10(XI) Y1.2(OSC2)
NetC33_2: C33.2 R32.1 TP39.1
NetC34_2: C34.2 R33.1 TP40.1
NetC35_2: C35.2 R34.1 TP41.1
NetC36_2: C36.2 R35.1 TP42.1
NetC38_1: C38.1 U2.6(VREF)
NetC39_2: C39.2 C40.1 U2.11(LDO)
NetD1_1: D1.1(A) R18.1
NetD2_2: D2.2(K) R20.1
NetD3_2: D3.2(K) R53.1
NetJ7_1: J7.1 R27.1 R28.1 R29.1 R30.1
NetJ8_1: J8.1 R36.1 R37.1 R38.1 R39.1
NetQ1_1: Q1.1(B) R47.1
NetQ1_3: Q1.3(C) R20.2
NetQ2_1: Q2.1(B) R58.1
NetQ2_3: Q2.3(C) R53.2
NetR40_2: R40.2 TP19.1
NetR41_2: R41.2 TP20.1
NetR42_2: R42.2 TP21.1
NetR43_2: R43.2 TP22.1
NetR49_2: R49.2 TP23.1
NetR50_2: R50.2 TP24.1
NetR51_2: R51.2 TP25.1
NetR52_2: R52.2 TP26.1
NetR54_2: R54.2 TP44.1
NetR55_2: R55.2 TP45.1
NetR56_2: R56.2 TP46.1
NetR57_2: R57.2 TP43.1
NetR59_2: R59.2 TP48.1
NetR60_2: R60.2 TP49.1
NetR61_2: R61.2 TP50.1
NetR62_2: R62.2 TP47.1

Not connected (* = marked no-connect by the designer): U1 26(MD0); U2 9(XO) 10(XI) 26(MD0)

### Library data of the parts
C7 C17 C23 C25 C29 C31 C37 C39 = GRM188R71C104KA01D: as C1 on sheet TIDA-01454B_Digital-IO
C8-C16 C18-C22 C30 C32-C36 = GRM21BR71A106KE51K: CAP, CERM, 10 µF, 10 V, +/- 10%, X7R, 0805; Manufacturer: MuRata; Polarized: N; CompType: Capacitor; Value: 10uF; U/M: EA; Cap_F: 0.00001; Tolerance_%: 10; Value1: Unknown; Value2: 10V; TaMin_C: -55; TaMax_C: 125; Cap_Case: 0805; SizeArea_mm2: 2.5; SizeAreaWB_mm2: 6.75; SizeX_mm: 2; SizeY_mm: 1.25; SizeZ_mm: 1.45; AEC Category: Q200
C24 C26 C38 C40 = GRM188R71C105KA12D: CAP, CERM, 1 µF, 16 V, +/- 10%, X7R, 0603; Manufacturer: MuRata; Polarized: N; CompType: Capacitor; Value: 1uF; U/M: EA; Cap_F: 0.000001; Tolerance_%: 10; ESR_ohm: 0.011; Value1: 0.011 ohm; VDC_V: 16; Value2: 16V; TaMin_C: -55; TaMax_C: 125; Cap_Case: 0603; SizeArea_mm2: 1.28; SizeAreaWB_mm2: 4.68; SizeX_mm: 1.6; SizeY_mm: 0.8; SizeZ_mm: 1; AEC Category: Q200
C27 C28 = GRM1885C1H180JA01D: CAP, CERM, 18 pF, 50 V, +/- 5%, C0G/NP0, 0603; Manufacturer: MuRata; Polarized: N; CompType: Capacitor; Value: 18pF; U/M: EA; Cap_F: 0.000000000018; Tolerance_%: 5; Value1: Unknown; VDC_V: 50; Value2: 50V; TaMin_C: -55; TaMax_C: 125; Cap_Case: 0603; SizeArea_mm2: 1.28; SizeAreaWB_mm2: 4.68; SizeX_mm: 1.6; SizeY_mm: 0.8; SizeZ_mm: 1; AEC Category: Q200
D1 = LTST-C171GKT: LED, Green, SMD; Manufacturer: Lite-On; Type: AlInGaP; Vf_V: 2.1; Value2: 2.1V; Io_A: 20; Value1: W; U/M: EA
D2 D3 = SMLP12BC7TT86: LED, Blue, SMD; Manufacturer: Rohm; Type: InGaN; Vf_V: 2.9; Value2: 2.9V; Io_A: 0.005; Tjmax_C: 85; Value1: W; U/M: EA
J7 J8 = JMP2-PBC02SAAN: Header, 100mil, 2x1, Gold, TH; Manufacturer: Sullins Connector Solutions; SymbolCreator: a0412235; U/M: EA
MIC1-MIC8 = SPH1642HT5H-1: Wide Bandwidth, Low Noise, Precision Top Port SiSonic Microphone, SMD; Manufacturer: Knowles Accoustics; SymbolCreator: Altium
Q1 Q2 = MMBT2222A, Fairchild Semiconductor: Transistor, NPN, 40 V, 0.15 A, SOT-23; CompType: BJT; PNP: 0; NPN: 1; Vceo_V: 40; Vcesat1_V: 0.3; Value: 40 V; IcRated_A: 0.15; Value1: 0.15 A; HfeMax: 300; TaMin_C: -55; TaMax_C: 150; U/M: EA; AEC Category: Q101
R18 = CRCW0402360RJNED: RES, 360, 5%, 0.063 W, 0402; Manufacturer: Vishay-Dale; CompType: Resistor; Value_Code: 360R; Tolerance_%: 5; Power_W: 0.063; Value2: 0.063W; VDC_V: 50; TempCo: 200 ppm/C; EIA_Code: E24; U/M: EA; AEC Category: Q200
R20 R53 = ERJ-2RKF1000X: RES, 100, 1%, 0.1 W, 0402; Manufacturer: Panasonic; CompType: Resistor; Value: 100; Value_Code: 100R; Tolerance_%: 1; Power_W: 0.1; Value2: 0.1W; VDC_V: 50; TempCo: 100 ppm/C; EIA_Code: E96; U/M: EA; AEC Category: Q200; SizeArea_mm2: 0.5; SizeZ_mm: 0.6
R22-R26 R31-R35 R44 R48 = CRCW06030000Z0EA: RES, 0, 5%, 0.1 W, 0603; Manufacturer: Vishay-Dale; CompType: Resistor; Value: 0; Value_Code: 0000; Tolerance_%: 5; Power_W: 0.1; Value2: 0.1W; VDC_V: 75; TempCo: 200 ppm/C; SizeArea_mm2: 1.28; SizeX_mm: 1.6; SizeY_mm: 0.8; SizeZ_mm: 1; EIA_Code: E24; U/M: EA; AEC Category: Q200
R27-R30 R36-R39 = CRCW04022K21FKED: as R14 on sheet TIDA-01454B_Digital-IO
R40-R43 R49-R52 R54-R57 R59-R62 = RC0402FR-0749R9L: as R1 on sheet TIDA-01454B_Digital-IO
R47 R58 = CRCW04022K15FKED: RES, 2.15 k, 1%, 0.063 W, 0402; Manufacturer: Vishay-Dale; CompType: Resistor; Value: 2.15k; Res_ohm: 2150; Value_Code: 2k15; Tolerance_%: 1; Power_W: 0.063; Value2: 0.063W; VDC_V: 50; TempCo: 100 ppm/C; EIA_Code: E96; U/M: EA; AEC Category: Q200; SizeArea_mm2: 0.5; SizeZ_mm: 0.6
TP7-TP54 = TestPoint_50x30-TH: as TP3 on sheet TIDA-01454B_Digital-IO
U1 U2 = PCM1864DBTR: Universal Microphone to 2VRMS Analog input, 24-Bit, 192 kHz Stereo Front-End, DBT0030A; Manufacturer: Texas Instruments; SymbolCreator: Altium; SizeArea_mm2: 49.92; SizeAreaWB_mm2: 82.32; SizeX_mm: 6.4; SizeY_mm: 7.8; SizeZ_mm: 1.2; CompType: IC; U/M: EA
Y1 = 9B-24.576MEEJ-B: Crystal, 24.576MHz, 18 pF, TH; Manufacturer: TXC Corporation; SymbolCreator: a0412235; SizeAreaWB_mm2: 94.5; SizeArea_mm2: 57.5; SizeX_mm: 11.5; SizeY_mm: 5; SizeZ_mm: 3.68; U/M: EA; TaMin_C: -20; TaMax_C: 70; Frequency Stability: ±10ppm

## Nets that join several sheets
3.3V: TIDA-01454B_Digital-IO (18 pins), TIDA-01454B_Main-IO (8 pins)
GND: TIDA-01454B_Digital-IO (33 pins), TIDA-01454B_Main-IO (74 pins)
BCKA: TIDA-01454B_Digital-IO (U5.2 U6.4), TIDA-01454B_Main-IO (U1.17)
BCKB: TIDA-01454B_Digital-IO (R11.1), TIDA-01454B_Main-IO (U2.17)
DMIN1A/INTA: TIDA-01454B_Digital-IO (J5.20), TIDA-01454B_Main-IO (R40.1 R41.1 U1.21)
DMIN1B/INTB: TIDA-01454B_Digital-IO (J5.19), TIDA-01454B_Main-IO (R54.1 R55.1 U2.21)
DMIN2A/SCKO: TIDA-01454B_Digital-IO (U3.2), TIDA-01454B_Main-IO (R42.1 R43.1 U1.22)
DOUT1A: TIDA-01454B_Digital-IO (J6.2), TIDA-01454B_Main-IO (U1.18)
DOUT1B: TIDA-01454B_Digital-IO (J6.4 R19.1), TIDA-01454B_Main-IO (U2.18)
DOUT2A: TIDA-01454B_Digital-IO (R45.1), TIDA-01454B_Main-IO (U1.19)
DOUT2B: TIDA-01454B_Digital-IO (R46.1), TIDA-01454B_Main-IO (U2.19)
LRCKA: TIDA-01454B_Digital-IO (U7.2 U8.4), TIDA-01454B_Main-IO (U1.16)
LRCKB: TIDA-01454B_Digital-IO (R21.1), TIDA-01454B_Main-IO (U2.16)
SCKIA: TIDA-01454B_Digital-IO (U4.4), TIDA-01454B_Main-IO (U1.15)
SCKIB: TIDA-01454B_Digital-IO (R10.1), TIDA-01454B_Main-IO (U2.15)
SCL: TIDA-01454B_Digital-IO (J3.1 J5.15 R14.2 TP3.1), TIDA-01454B_Main-IO (U1.24 U2.24)
SDA: TIDA-01454B_Digital-IO (J3.2 J5.18 R15.2 TP4.1), TIDA-01454B_Main-IO (U1.23 U2.23)

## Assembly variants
001: not fitted FID1 FID2 FID3 J1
